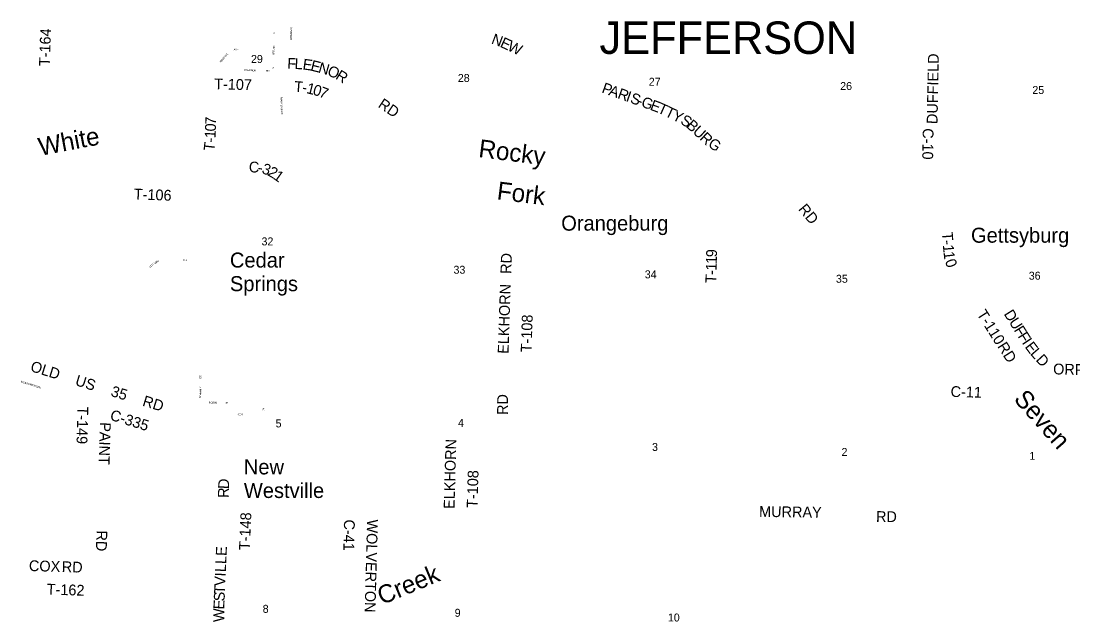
# Model space of a CAD drawing. Extents: x -21.9 to 47.3, y 14.1 to 48.7.
# Drawn here: x 2.168 to 6.341, y 16.612 to 18.997 of the extents above; entities that cross this region are included whole.
import ezdxf

# ---------------------------------------------------------------- set-up
doc = ezdxf.new("R2010")
doc.units = 0
for name, color, linetype in [('GM_X_City_Street_Text', 7, 'Continuous'), ('GM_X_County_Road_Text', 7, 'Continuous'), ('GM_X_Major_River_Text', 7, 'Continuous'), ('GM_X_Minor_River_Text', 7, 'Continuous'), ('GM_X_Section_Text', 7, 'Continuous'), ('GM_X_Township_Road_Text', 7, 'Continuous'), ('GM_X_Township_Subdivision_Text', 7, 'Continuous'), ('GM_X_Township_Text', 7, 'Continuous'), ('GM_X_Unincorporated_Text', 7, 'Continuous')]:
    doc.layers.add(name, color=color, linetype=linetype)

msp = doc.modelspace()

# ---------------------------------------------------------------- texts
at = {"layer": 'GM_X_City_Street_Text'}
for s, rotation, p in [('ST', 90, (3.1755, 18.9453)), ('O', 89.1011, (3.2425, 18.9428)), ('N', 89.1011, (3.2427, 18.9541)), ('L', 89.1018, (3.2426, 18.9491)), ('S', 84.6, (3.2428, 18.9621)), ('T', 79.9056, (3.2432, 18.967)), ('L', 89.1018, (3.2422, 18.9227)), ('I', 89.0987, (3.2423, 18.9277)), ('C', 89.1014, (3.2424, 18.9371)), ('N', 89.1011, (3.2423, 18.9308)), ('KRISTINE', 49.4974, (2.9609, 18.8318)), ('AVE', 0, (3.0116, 18.8806)), ('SPRING', 88.0587, (3.173, 18.8617)), ('FLEENOR', 357.2752, (3.0544, 18.7995)), ('RD', 356.9888, (3.1386, 18.7964)), ('S', 90, (3.1718, 18.8089)), ('S', 271.4656, (3.1971, 18.6964)), ('H', 271.4643, (3.1972, 18.6914)), ('A', 271.4671, (3.1974, 18.6851)), ('D', 271.4643, (3.1975, 18.6788)), ('Y', 271.4671, (3.1977, 18.6725)), ('L', 271.4656, (3.1979, 18.6644)), ('A', 271.4643, (3.198, 18.6593)), ('N', 272.0767, (3.1982, 18.653)), ('E', 274.7019, (3.1985, 18.6463)), ('D', 275.354, (3.199, 18.6393)), ('R', 275.3536, (3.1996, 18.6331))]:
    msp.add_text(s, height=0.00714, rotation=rotation, dxfattribs=at).set_placement(p)
at = {"layer": 'GM_X_County_Road_Text'}
for s, height, rotation, p in [('N', 0.0429, 339.4582, (4.0306, 18.9088)), ('E', 0.0429, 335.2466, (4.0651, 18.8959)), ('W', 0.0429, 334.7864, (4.0941, 18.8825)), ('DUFFIELD', 0.04286, 88.8627, (5.8032, 18.588)), ('P', 0.0429, 340.4559, (4.4685, 18.714)), ('A', 0.0429, 340.4549, (4.4957, 18.7043)), ('R', 0.0429, 340.4567, (4.5313, 18.6917)), ('I', 0.0429, 340.452, (4.5644, 18.6799)), ('S', 0.0429, 340.4573, (4.581, 18.674)), ('G', 0.0429, 340.4125, (4.6249, 18.6585)), ('-', 0.0429, 340.452, (4.6083, 18.6644)), ('E', 0.0429, 339.4362, (4.6602, 18.6459)), ('T', 0.0429, 335.9522, (4.6896, 18.6349)), ('T', 0.0429, 333.9464, (4.7185, 18.622)), ('Y', 0.0429, 333.6954, (4.7473, 18.6079)), ('S', 0.0429, 329.7383, (4.7804, 18.5916)), ('B', 0.0429, 318.0051, (4.8035, 18.5784)), ('U', 0.0429, 317.0553, (4.8295, 18.555)), ('R', 0.0429, 317.3183, (4.8573, 18.5291)), ('G', 0.0429, 328.0217, (4.8901, 18.5)), ('C-10', 0.04286, 268.9711, (5.745, 18.572)), ('C', 0.0429, 357.9542, (3.0709, 18.3969)), ('-', 0.0429, 352.3341, (3.1049, 18.3958)), ('3', 0.0429, 341.0939, (3.1202, 18.3939)), ('2', 0.0429, 329.8537, (3.1432, 18.3863)), ('1', 0.0429, 324.2336, (3.1651, 18.3736)), ('RD', 0.04286, 309.7419, (5.2491, 18.2496)), ('OLD', 0.04286, 342.6252, (2.202, 17.6087)), ('US', 0.04286, 342.7403, (2.3798, 17.5528)), ('35', 0.04286, 343.3019, (2.5211, 17.5095)), ('C-11', 0.04286, 358.2847, (5.8549, 17.5056)), ('RD', 0.04286, 342.9697, (2.6469, 17.4711)), ('C-335', 0.04286, 342.9588, (2.5177, 17.4152)), ('C-41', 0.04286, 268.6278, (3.4494, 17.0192)), ('WOLVERTON', 0.04286, 268.4811, (3.5407, 17.0195))]:
    msp.add_text(s, height=height, rotation=rotation, dxfattribs=at).set_placement(p)
at = {"layer": 'GM_X_Major_River_Text'}
msp.add_text('Seven', height=0.07147, rotation=311.4228, dxfattribs=at).set_placement((6.1027, 17.4948))
at = {"layer": 'GM_X_Minor_River_Text'}
for s, height, rotation, p in [('White', 0.07142, 10.8265, (2.2443, 18.462)), ('Rocky', 0.07142, 352.8911, (3.9802, 18.4574)), ('Fork', 0.07142, 352.8908, (4.0531, 18.2897)), ('Creek', 0.07146, 22.5161, (3.5997, 16.6791))]:
    msp.add_text(s, height=height, rotation=rotation, dxfattribs=at).set_placement(p)
at = {"layer": 'GM_X_Section_Text'}
for s, height, p in [('29', 0.03157, (3.0801, 18.8309)), ('28', 0.03157, (3.9007, 18.7555)), ('27', 0.03157, (4.6581, 18.7404)), ('26', 0.03157, (5.4174, 18.7234)), ('25', 0.03157, (6.1796, 18.7077)), ('32', 0.03157, (3.1219, 18.1068)), ('33', 0.03157, (3.8834, 17.9943)), ('34', 0.03157, (4.6421, 17.9761)), ('35', 0.03157, (5.4005, 17.9585)), ('36', 0.03157, (6.1654, 17.9707)), ('5', 0.0316, (3.1778, 17.3844)), ('4', 0.0316, (3.9013, 17.3864)), ('3', 0.0316, (4.671, 17.2909)), ('2', 0.0316, (5.4228, 17.2711)), ('1', 0.0316, (6.1679, 17.2557)), ('8', 0.0316, (3.1266, 16.6485)), ('9', 0.0316, (3.8881, 16.6328)), ('10', 0.03157, (4.7339, 16.614))]:
    msp.add_text(s, height=height, rotation=0, dxfattribs=at).set_placement(p)
at = {"layer": 'GM_X_Township_Road_Text'}
for s, height, rotation, p in [('T-164', 0.04286, 88.0347, (2.282, 18.8176)), ('F', 0.0429, 357.6807, (3.2234, 18.8081)), ('L', 0.0429, 356.9601, (3.2521, 18.807)), ('E', 0.0429, 352.1759, (3.2832, 18.8054)), ('E', 0.0429, 346.2619, (3.3138, 18.8012)), ('N', 0.0429, 344.2969, (3.3445, 18.7937)), ('O', 0.0429, 336.5233, (3.3794, 18.784)), ('R', 0.0429, 327.664, (3.4124, 18.7698)), ('T-107', 0.04286, 358.6025, (2.9337, 18.7264)), ('T', 0.0429, 355.8565, (3.25, 18.7164)), ('1', 0.0429, 346.0084, (3.2974, 18.7116)), ('0', 0.0429, 344.5285, (3.3227, 18.7053)), ('7', 0.0429, 338.389, (3.347, 18.6986)), ('-', 0.0429, 350.8516, (3.281, 18.7142)), ('RD', 0.04286, 326.1729, (3.581, 18.6576)), ('7', 0.0429, 87.826, (2.9413, 18.5848)), ('0', 0.0429, 87.7611, (2.9403, 18.5583)), ('1', 0.0429, 87.5051, (2.9391, 18.5317)), ('-', 0.0429, 86.9684, (2.9382, 18.5137)), ('T', 0.0429, 83.5168, (2.9343, 18.4791)), ('T-106', 0.04286, 357.7544, (2.6146, 18.2895)), ('T', 0.0429, 274.3476, (5.8207, 18.1583)), ('-', 0.0429, 274.4531, (5.8231, 18.1263)), ('RD', 0.04286, 88.025, (4.1123, 17.993)), ('9', 0.0429, 88.7255, (4.9283, 18.0594)), ('1', 0.0429, 274.8932, (5.8245, 18.1084)), ('1', 0.0429, 276.754, (5.8269, 18.0806)), ('1', 0.0429, 88.6114, (4.927, 18.0065)), ('1', 0.0429, 88.7063, (4.9277, 18.033)), ('0', 0.0429, 289.4485, (5.8323, 18.0443)), ('T', 0.0429, 87.1987, (4.9249, 17.9558)), ('-', 0.0429, 88.3772, (4.9265, 17.9888)), ('ELKHORN', 0.04286, 88.1291, (4.1016, 17.676)), ('T-108', 0.04286, 88.0346, (4.1928, 17.6818)), ('T-110', 0.04286, 302.2133, (5.9576, 17.8345)), ('D', 0.0429, 302.0488, (6.0651, 17.8349)), ('U', 0.0429, 302.0488, (6.0851, 17.8029)), ('F', 0.0429, 302.0488, (6.1051, 17.7709)), ('F', 0.0429, 302.0488, (6.1205, 17.7464)), ('I', 0.0429, 303.7884, (6.1366, 17.7208)), ('RD', 0.04286, 302.3199, (6.0394, 17.706)), ('E', 0.0429, 307.2676, (6.148, 17.7039)), ('L', 0.0429, 310.7469, (6.1691, 17.6762)), ('D', 0.0429, 312.4865, (6.191, 17.6508)), ('ORPHANS', 0.04286, 358.6748, (6.2617, 17.595)), ('RD', 0.04286, 89.5152, (4.0991, 17.4335)), ('T-149', 0.04286, 268.3153, (2.3923, 17.4684)), ('PAINT', 0.04286, 268.1298, (2.4814, 17.4054)), ('ELKHORN', 0.04286, 88.4209, (3.8873, 17.0606)), ('T-108', 0.04286, 88.3153, (3.9785, 17.0643)), ('D', 0.0429, 87.7219, (2.9924, 17.139)), ('R', 0.0429, 88.6192, (2.9916, 17.104)), ('MURRAY', 0.04286, 359.2172, (5.0955, 17.0293)), ('T-148', 0.04286, 87.4987, (3.0752, 16.8966)), ('RD', 0.04286, 359.5064, (5.5593, 17.0092)), ('RD', 0.04286, 268.0251, (2.4676, 16.976)), ('E', 0.0429, 87.4278, (2.9831, 16.8735)), ('L', 0.0429, 87.4273, (2.9817, 16.8414)), ('COX', 0.04286, 358.3724, (2.1987, 16.8143)), ('RD', 0.04286, 358.0243, (2.3289, 16.8105)), ('L', 0.0429, 87.4278, (2.9802, 16.8094)), ('V', 0.0429, 87.4274, (2.9778, 16.7542)), ('I', 0.0429, 87.4255, (2.9794, 16.7918)), ('T-162', 0.04286, 358.0347, (2.2692, 16.7212)), ('T', 0.0429, 87.4278, (2.9763, 16.7221)), ('E', 0.0429, 87.6069, (2.9737, 16.6612)), ('S', 0.0429, 87.4273, (2.975, 16.6932)), ('W', 0.0429, 90.3574, (2.974, 16.6121))]:
    msp.add_text(s, height=height, rotation=rotation, dxfattribs=at).set_placement(p)
at = {"layer": 'GM_X_Township_Subdivision_Text'}
for s, height, rotation, p in [('L', 0.00714, 39.046, (2.6845, 18.0222)), ('D', 0.00714, 34.9883, (2.6883, 18.0253)), ('U', 0.00714, 34.1045, (2.6978, 18.0312)), ('S', 0.00714, 34.0784, (2.703, 18.0347)), ('4', 0.00714, 34.1198, (2.7072, 18.0375)), ('0', 0.00714, 32.5025, (2.7108, 18.04)), ('RD', 0.00714, 356.9889, (2.8124, 18.0453)), ('O', 0.00714, 60.9744, (2.6819, 18.0172)), ('MEADOWCREST', 0.007143, 342.5813, (2.1672, 17.5631)), ('DR', 0.00714, 90, (2.8827, 17.5781)), ('LN', 0.00714, 344.4726, (2.2331, 17.5417)), ('Y', 0.00714, 90, (2.8834, 17.54)), ('L', 0.00714, 90, (2.8834, 17.535)), ('R', 0.00714, 90, (2.8834, 17.5293)), ('E', 0.00714, 90.0009, (2.8834, 17.5243)), ('K', 0.00714, 79.0461, (2.8802, 17.5005)), ('I', 0.00714, 79.0505, (2.8814, 17.5067)), ('M', 0.00714, 81.5998, (2.8821, 17.5101)), ('B', 0.00714, 89.2133, (2.8833, 17.5186)), ('ROBIN', 0.00714, 0, (2.9129, 17.4789)), ('DR', 0.00714, 0, (2.9758, 17.4783)), ('LN', 0.00714, 86.82, (3.1322, 17.4481)), ('KEN', 0.00714, 0, (3.026, 17.4324))]:
    msp.add_text(s, height=height, rotation=rotation, dxfattribs=at).set_placement(p)
at = {"layer": 'GM_X_Township_Text'}
msp.add_text('JEFFERSON', height=0.12857, rotation=0, dxfattribs=at).set_placement((4.4627, 18.8668))
at = {"layer": 'GM_X_Unincorporated_Text'}
for s, p in [('Orangeburg', (4.3108, 18.1652)), ('Gettsyburg', (5.9363, 18.1174)), ('Cedar', (2.9965, 18.0187)), ('Springs', (2.9965, 17.9251)), ('New', (3.0518, 17.1978)), ('Westville', (3.0518, 17.1042))]:
    msp.add_text(s, height=0.05957, rotation=0, dxfattribs=at).set_placement(p)

doc.saveas('drawing.dxf')
